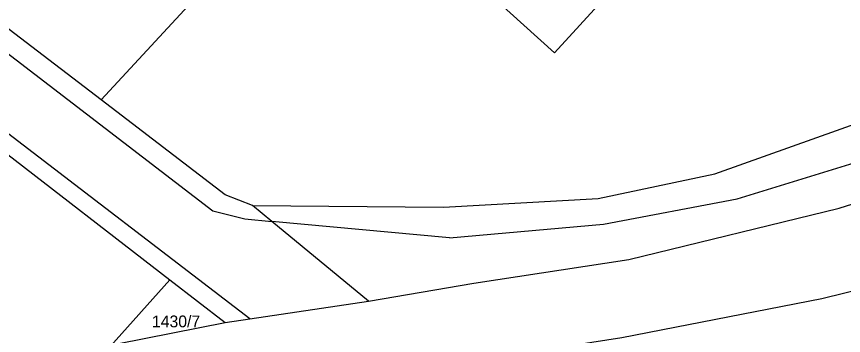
# Model space of a CAD drawing. Extents: x -679220 to -673243, y -1075091 to -1066557.
# Drawn here: x -677237.5 to -677157.5, y -1070750.8 to -1070720 of the extents above; entities that cross this region are included whole.
import ezdxf

# ---------------------------------------------------------------- set-up
doc = ezdxf.new("R2010")
doc.units = 0
for name, color, linetype in [('Hranice parcel', 7, 'Continuous'), ('Parcelní čísla', 7, 'Continuous'), ('Vnitřní kresba', 7, 'Continuous')]:
    doc.layers.add(name, color=color, linetype=linetype)

msp = doc.modelspace()

# ---------------------------------------------------------------- linework, layer by layer
at = {"layer": 'Hranice parcel'}
for p, q in [((-677254.95, -1070720.42), (-677222.65, -1070745.38)), ((-677228.39, -1070751.81), (-677222.65, -1070745.38)), ((-677222.65, -1070745.38), (-677217.29, -1070749.51))]:
    msp.add_line(p, q, dxfattribs=at)
for points in [[(-677229.27, -1070728.01), (-677278.26, -1070690.56), (-677374.15, -1070617.77), (-677453.8, -1070557.3)], [(-677167.2, -1070661), (-677176.61, -1070671.11), (-677229.27, -1070728.01)], [(-677214.66, -1070738.21), (-677196.21, -1070738.39), (-677181.24, -1070737.55), (-677169.99, -1070735.15), (-677135.71, -1070722.94), (-677130.32, -1070719.97), (-677115.15, -1070707.42), (-677105.41, -1070699.25), (-677097.57, -1070693.96), (-677085.89, -1070686.8), (-677075.41, -1070680.75), (-677067.64, -1070676.6)], [(-677214.66, -1070738.21), (-677217.29, -1070737.17), (-677229.27, -1070728.01)], [(-677203.43, -1070747.44), (-677193.26, -1070745.7), (-677178.28, -1070743.44), (-677157.97, -1070738.48), (-677150.43, -1070736.08), (-677143.78, -1070733.71), (-677136.41, -1070730.21), (-677135.39, -1070729.77)], [(-677203.43, -1070747.44), (-677212.79, -1070739.75), (-677214.66, -1070738.21)], [(-677141.72, -1070742.83), (-677159.64, -1070747.23), (-677178.96, -1070751), (-677188.07, -1070752.41)], [(-677217.29, -1070749.51), (-677214.9, -1070749.15), (-677203.43, -1070747.44)], [(-677228.39, -1070751.81), (-677227.56, -1070751.54), (-677217.29, -1070749.51)]]:
    msp.add_lwpolyline(points, dxfattribs=at)
at = {"layer": 'Vnitřní kresba'}
for p, q in [((-677150.16, -1070684.57), (-677185.46, -1070723.48)), ((-677279.29, -1070692.15), (-677218.48, -1070738.73)), ((-677214.9, -1070749.15), (-677282.66, -1070697.35)), ((-677185.46, -1070723.48), (-677202.82, -1070707.75)), ((-677167.81, -1070737.56), (-677155.25, -1070733.7)), ((-677180.75, -1070740), (-677167.81, -1070737.56)), ((-677218.48, -1070738.73), (-677215.39, -1070739.51)), ((-677215.39, -1070739.51), (-677212.79, -1070739.75)), ((-677195.62, -1070741.33), (-677212.79, -1070739.75)), ((-677195.62, -1070741.33), (-677180.75, -1070740))]:
    msp.add_line(p, q, dxfattribs=at)

# ---------------------------------------------------------------- texts
at = {"layer": 'Parcelní čísla'}
msp.add_text('1430/7', height=1.14, dxfattribs=at).set_placement((-677224.37, -1070749.979))

doc.saveas('drawing.dxf')
